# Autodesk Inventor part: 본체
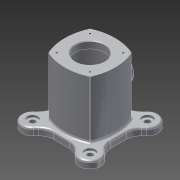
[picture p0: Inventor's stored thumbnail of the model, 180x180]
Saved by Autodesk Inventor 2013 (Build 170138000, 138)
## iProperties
Created: 2016-05
Part Number: 본체
Material: 알루미늄 6061
Document SubType Name: Modeling
Designer: Administrator
Density: 2.71 g/cm^3
Mass: 1110.84 g
Surface Area: 862.718 cm^2
Volume: 409.905 cm^3
Author: Administrator
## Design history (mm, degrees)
sketch "스케치1"
  geometry: L1 (-35.355, 35.355)-(35.355, 35.355); L2 (35.355, 35.355)-(35.355, -35.355); L3 (35.355, -35.355)-(-35.355, -35.355); L4 (-35.355, -35.355)-(-35.355, 35.355); L5 (-35.355, 35.355)-(35.355, -35.355); L6 (35.355, 35.355)-(-35.355, -35.355); A1 r 85.579 centre (0, -42.579) between (35.355, 35.355) and (-35.355, 35.355); A2 r 85.579 centre (0, 42.579) between (-35.355, -35.355) and (35.355, -35.355); A3 r 85.579 centre (-42.579, 0) between (35.355, -35.355) and (35.355, 35.355); A4 r 85.579 centre (42.579, 0) between (-35.355, 35.355) and (-35.355, -35.355); 3 further points
  constraints: 12 end point, 8 point on circle, 4 centre point, 3 equal radius, 3 midpoint, 2 parallel, 1 coincident, 1 horizontal, 1 perpendicular
  dimensions: "d1" = 86 dimension on A2 A1; "d3" = 100 distance of L2.end L1.start; "d4" = 86 dimension on A3 A4; "d5" = 100 distance of L1.end L3.end (derived)
extrude "돌출1" new body sketch "스케치1" distance "d6" = 98; taper "d7" = 0 deg
sketch "스케치2"
  geometry: L1 (-49, 49)-(49, 49); L2 (49, 49)-(49, -49); L3 (49, -49)-(-49, -49); L4 (-49, -49)-(-49, 49); L5 (-49, 49)-(49, -49); L6 (49, 49)-(-49, -49); L7 (0, 0)-(-65.815, 65.815); L8 (1.907, 1.907)-(59.318, 59.318); L9 (0, 0)-(0, 85.87); L10 (60.523, 35.171)-(41.469, 16.117); L11 (35.171, 60.523)-(23.649, 49); L12 (-35.171, 60.523)-(-23.649, 49); L13 (-60.523, 35.171)-(-41.469, 16.117); L14 (0, 0)-(67, 0); L15 (35.171, -60.523)-(23.649, -49); L16 (60.523, -35.171)-(41.469, -16.117); L17 (-60.523, -35.171)-(-41.469, -16.117); L18 (-35.171, -60.523)-(-23.649, -49); L19 (-49, 23.649)-(-49, -23.649); L20 (-23.649, -49)-(23.649, -49); L21 (49, -23.649)-(49, 23.649); L22 (23.649, 49)-(-23.649, 49); A1 r 85.579 centre (-42.579, 0) between (35.355, -35.355) and (35.355, 35.355) reference; A2 r 70 centre (0, 0) between (35.171, 60.523) and (60.523, 35.171); A3 r 18 centre (49, 49) between (35.171, 60.523) and (60.523, 35.171); A4 r 18 centre (-49, 49) between (-35.171, 60.523) and (-60.523, 35.171); A5 r 18 centre (49, -49) between (35.171, -60.523) and (60.523, -35.171); A6 r 18 centre (-49, -49) between (-35.171, -60.523) and (-60.523, -35.171); 1 further point
  constraints: 44 end point, 15 symmetric about line, 11 point on circle, 10 point on line, 5 centre point, 5 parallel, 2 coincident, 2 collinear, 2 midpoint, 2 perpendicular, 1 horizontal, 3 other
  dimensions: "d8" = 140 diameter of A2; "d10" = 98 distance of L1.start L1.end; "d11" = 98 distance of L1.end L2.end; "d12" = 45 deg angle of L8 L9; "d13" = 45 deg angle of L7 L9; "d14" = 36 diameter of A3
extrude "돌출2" join sketch "스케치2" distance "d15" = 12; taper "d16" = 0 deg
sketch "스케치3"
  geometry: L1 (-60.523, 35.171)-(-49, 23.649) reference; L2 (-49, 23.649)-(-49, -23.649) reference; L3 (-49, -23.649)-(-60.523, -35.171) reference; L4 (-35.171, -60.523)-(-23.649, -49) reference; L5 (-23.649, -49)-(23.649, -49) reference; L6 (23.649, -49)-(35.171, -60.523) reference; L7 (60.523, -35.171)-(49, -23.649) reference; L8 (49, -23.649)-(49, 23.649) reference; L9 (49, 23.649)-(60.523, 35.171) reference; L10 (35.171, 60.523)-(23.649, 49) reference; L11 (23.649, 49)-(-23.649, 49) reference; L12 (-23.649, 49)-(-35.171, 60.523) reference; A1 r 18 centre (-49, 49) between (-35.171, 60.523) and (-60.523, 35.171) reference; A2 r 18 centre (-49, -49) between (-60.523, -35.171) and (-35.171, -60.523) reference; A3 r 18 centre (49, -49) between (35.171, -60.523) and (60.523, -35.171) reference; A4 r 18 centre (49, 49) between (60.523, 35.171) and (35.171, 60.523) reference; 1 further point
node "작업 평면1"
sketch "스케치4"
  geometry: L1 (35.355, 98)-(-35.355, 98) reference; L2 (23.649, 0)-(-23.649, 0) reference; L3 (43, 0)-(43, 98) reference; C1 r 20 at (0, 49); 2 further points
  constraints: 1 centre point, 1 midpoint, 1 vertical alignment
  dimensions: "d18" = 49 distance of C1.centre point (0, 0); "d19" = 40 diameter of C1
extrude "돌출3" join sketch "스케치4" stored distance "d20" = 12; taper "d21" = 10 deg
sketch "스케치5"
  geometry: C1 r 20 at (0, 0) reference; 1 further point
hole "구멍1" sketch "스케치5" at (0, 0) diameter "d22" = 25; stored, may be unused: countersink angle "d26" = 90 deg, drill point angle "d28" = 118 deg; dims "d23" = 6, "d24" = 30, "d25" = 8, "d27" = 30
sketch "스케치6"
  geometry: C1 r 25 at (0, 0); 1 further point
  constraints: 1 centre point, 1 coincident
  dimensions: "d29" = 50 diameter of C1
extrude "돌출4" cut sketch "스케치6" distance "d31" = 12; taper "d32" = 0 deg
sketch "스케치7"
  geometry: C1 r 25 at (0, 0) reference
hole "구멍2" sketch "스케치7" at (0, 0) diameter "d33" = 50; stored, may be unused: countersink angle "d37" = 90 deg, drill point angle "d39" = 0 deg; dims "d34" = 6, "d35" = 70, "d36" = 86, "d38" = 98
sketch "스케치8"
  geometry: A1 r 18 centre (49, 49) between (60.523, 35.171) and (35.171, 60.523) reference; A2 r 18 centre (-49, 49) between (-35.171, 60.523) and (-60.523, 35.171) reference; A3 r 18 centre (-49, -49) between (-60.523, -35.171) and (-35.171, -60.523) reference; A4 r 18 centre (49, -49) between (35.171, -60.523) and (60.523, -35.171) reference; 1 further point
hole "구멍3" sketch "스케치8" at (-49, 49), (-49, -49), (49, 49), (49, -49) diameter "d40" = 10; stored, may be unused: countersink angle "d44" = 90 deg, drill point angle "d46" = 0 deg; dims "d41" = 6, "d42" = 18, "d43" = 4, "d45" = 98
sketch "스케치9"
  geometry: L1 (23.649, 49)-(-23.649, 49) reference; L2 (0, 0)-(-28.284, 28.284); L3 (0, 0)-(0, 61.728); C1 r 25 at (0, 0) reference
  constraints: 4 end point, 1 perpendicular
  dimensions: "d47" = 40 distance of L2.start L2.end; "d48" = 45 deg angle of L2 L3
hole "구멍4" sketch "스케치9" at (-28.284, 28.284) diameter "d49" = 3.242; stored, may be unused: countersink angle "d53" = 90 deg, drill point angle "d55" = 118 deg; dims "d50" = 7, "d51" = 18, "d52" = 4, "d54" = 10
sketch "스케치10"
  geometry: L1 (0, 0)-(0, 75.036); L2 (0, 0)-(-28.284, 28.284); C1 r 25 at (0, 0) reference
  constraints: 4 end point, 1 vertical
  dimensions: "d59" = 45 deg angle of L2 L1; "d60" = 40 distance of L1.start L2.end
hole "구멍5" sketch "스케치10" at (-28.284, 28.284) diameter "d61" = 3.242; stored, may be unused: countersink angle "d65" = 90 deg, drill point angle "d67" = 118 deg; dims "d62" = 7, "d63" = 18, "d64" = 4, "d66" = 10
chamfer "모따기1" distance "d71" = 1; stored, may be unused: second distance "d72" = 2, angle "d73" = 45 deg
fillet "모깎기1" dims "d74" = 3, "d75" = 25
fillet "모깎기2" dims "d76" = 3
node "작업 평면2"
sketch "스케치11"
  geometry: L1 (0, 0)-(29, 37.937); A1 r 85.579 centre (0, -42.579) between (34.285, 35.832) and (-34.285, 35.832) reference
  constraints: 2 end point, 1 point on circle
  dimensions: "d78" = 29 horizontal distance of L1.end A1.centre
node "작업 평면3"
sketch "스케치12"
  geometry: 3 further points; 1 other entity
  constraints: 1 horizontal alignment, 2 other
feature "엠보싱1" sketch "스케치12" dims "d1" = 86, "d3" = 100, "d4" = 86, "d5" = 100 (derived), "d8" = 140, "d10" = 98, "d11" = 98, "d12" = 45 deg, "d13" = 45 deg, "d14" = 36, "d80" = 0.5, "d81" = 0
node "솔리드1"
pattern_circular "원형 패턴1" dims angle "d57" = 360 deg
pattern_circular "원형 패턴2" dims angle "d69" = 360 deg
other parameters: "d17" = 55, "d77" = 49
